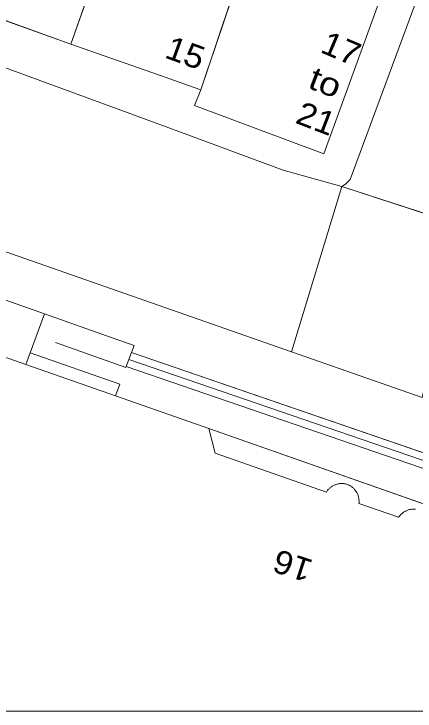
# Model space of a CAD drawing. Extents: x 528790 to 529292, y 179350 to 179856.
# Drawn here: x 529100.89 to 529126.67, y 179356.02 to 179400.83 of the extents above; entities that cross this region are included whole.
import ezdxf

# ---------------------------------------------------------------- set-up
doc = ezdxf.new("R2010")
doc.units = 0
doc.header["$LTSCALE"] = 0.6
for name, color, linetype, lineweight in [('1', 7, 'Continuous', 13), ('2', 7, 'Continuous', 13), ('7', 7, 'Continuous', 13)]:
    doc.layers.add(name, color=color, linetype=linetype, lineweight=lineweight)
doc.layers.add('5', color=7, linetype='Continuous')

msp = doc.modelspace()

# ---------------------------------------------------------------- linework, layer by layer
at = {"layer": '1'}
for points in [[(529153.4, 179460.25), (529147, 179461.55), (529147.5, 179461.3), (529147.9, 179460.65), (529148, 179460.25), (529148.15, 179459.8), (529148.05, 179459.25), (529122.5, 179390.2), (529122.2, 179389.9), (529121.95, 179389.75), (529129.75, 179387.2), (529129.6, 179387.45), (529129.55, 179387.75), (529129.55, 179388), (529129.6, 179388.25), (529151.6, 179448.1)], [(529080, 179405.2), (529096.7, 179398.7), (529108.8, 179394.254), (529111.481, 179393.269), (529118.2, 179390.8), (529121.95, 179389.75), (529122.2, 179389.9), (529122.5, 179390.2), (529148.05, 179459.25)], [(529126.2, 179406.7), (529120.8, 179391.85), (529112.5, 179394.95), (529112.9, 179395.95), (529112.105, 179396.231), (529110.606, 179396.76), (529104.55, 179398.9), (529081.7, 179407.1)], [(529082.78, 179391.7), (529118.73, 179379.12), (529121.95, 179389.75), (529118.2, 179390.8), (529111.481, 179393.269), (529108.8, 179394.254), (529096.7, 179398.7)], [(529127.13, 179376.18), (529118.73, 179379.12), (529082.78, 179391.7)], [(529084.94, 179384.18), (529101.65, 179378.31), (529101.93, 179379.06), (529102.86, 179381.55), (529088.9, 179386.48)], [(529088.21, 179386.8), (529088.54, 179386.66), (529088.9, 179386.48), (529102.86, 179381.55), (529107.2, 179380.02), (529108.61, 179379.52), (529108.44, 179379.07), (529135.26, 179369.85), (529135.32, 179370.03), (529140.32, 179368.27), (529140.62, 179368.17), (529140.91, 179368.05), (529141.19, 179367.93), (529141.47, 179367.79), (529141.79, 179367.61), (529142.06, 179367.45), (529142.32, 179367.28), (529142.67, 179367.02)], [(529113.41, 179374.18), (529107.42, 179376.28), (529101.65, 179378.31), (529084.94, 179384.18)], [(529134.94, 179368.95), (529108.11, 179378.17), (529108.44, 179379.07), (529108.61, 179379.52), (529107.2, 179380.02), (529102.86, 179381.55), (529101.93, 179379.06), (529107.69, 179377.03), (529107.42, 179376.28), (529113.41, 179374.18), (529135.36, 179366.48)], [(529126.7, 179369.01), (529126.65, 179369.01), (529126.6, 179369.01), (529126.55, 179369.01), (529126.5, 179369.01), (529126.45, 179369), (529126.4, 179368.99), (529126.35, 179368.98), (529126.3, 179368.97), (529126.25, 179368.95), (529126.2, 179368.94), (529126.15, 179368.92), (529126.11, 179368.9), (529126.06, 179368.88), (529126.02, 179368.85), (529125.97, 179368.83), (529125.93, 179368.8), (529125.89, 179368.77), (529125.85, 179368.74), (529125.81, 179368.71), (529125.77, 179368.67), (529125.74, 179368.64), (529125.7, 179368.6), (529125.67, 179368.56), (529125.64, 179368.52), (529125.61, 179368.48), (529123.06, 179369.37), (529123.07, 179369.42), (529123.07, 179369.47), (529123.07, 179369.52), (529123.07, 179369.56), (529123.06, 179369.61), (529123.06, 179369.66), (529123.05, 179369.71), (529123.04, 179369.75), (529123.03, 179369.8), (529123.01, 179369.85), (529123, 179369.89), (529122.98, 179369.94), (529122.96, 179369.98), (529122.94, 179370.02), (529122.92, 179370.07), (529122.89, 179370.11), (529122.87, 179370.15), (529122.84, 179370.19), (529122.81, 179370.23), (529122.78, 179370.27), (529122.75, 179370.3), (529122.71, 179370.34), (529122.68, 179370.37), (529122.64, 179370.4), (529122.61, 179370.43), (529122.57, 179370.46), (529122.53, 179370.49), (529122.49, 179370.51), (529122.44, 179370.53), (529122.4, 179370.55), (529122.36, 179370.57), (529122.31, 179370.59), (529122.22, 179370.62), (529122.18, 179370.63), (529122.13, 179370.63), (529122.08, 179370.64), (529122.03, 179370.64), (529121.98, 179370.65), (529121.94, 179370.65), (529121.89, 179370.64), (529121.84, 179370.64), (529121.79, 179370.63), (529121.75, 179370.63), (529121.7, 179370.62), (529121.65, 179370.6), (529121.6, 179370.59), (529121.56, 179370.57), (529121.51, 179370.56), (529121.47, 179370.54), (529121.43, 179370.52), (529121.38, 179370.49), (529121.34, 179370.47), (529121.3, 179370.44), (529121.26, 179370.42), (529121.22, 179370.39), (529121.19, 179370.36), (529121.15, 179370.32), (529121.12, 179370.29), (529121.08, 179370.26), (529121.05, 179370.22), (529121.02, 179370.18), (529121, 179370.14), (529120.97, 179370.1), (529113.83, 179372.61), (529113.41, 179374.18)], [(529113.41, 179374.18), (529113.83, 179372.61), (529120.97, 179370.1), (529121, 179370.14), (529121.02, 179370.18), (529121.05, 179370.22), (529121.08, 179370.26), (529121.12, 179370.29), (529121.15, 179370.32), (529121.19, 179370.36), (529121.22, 179370.39), (529121.26, 179370.42), (529121.3, 179370.44), (529121.34, 179370.47), (529121.38, 179370.49), (529121.43, 179370.52), (529121.47, 179370.54), (529121.51, 179370.56), (529121.56, 179370.57), (529121.6, 179370.59), (529121.65, 179370.6), (529121.7, 179370.62), (529121.75, 179370.63), (529121.79, 179370.63), (529121.84, 179370.64), (529121.89, 179370.64), (529121.94, 179370.65), (529121.98, 179370.65), (529122.03, 179370.64), (529122.08, 179370.64), (529122.13, 179370.63), (529122.18, 179370.63), (529122.22, 179370.62), (529122.31, 179370.59), (529122.36, 179370.57), (529122.4, 179370.55), (529122.44, 179370.53), (529122.49, 179370.51), (529122.53, 179370.49), (529122.57, 179370.46), (529122.61, 179370.43), (529122.64, 179370.4), (529122.68, 179370.37), (529122.71, 179370.34), (529122.75, 179370.3), (529122.78, 179370.27), (529122.81, 179370.23), (529122.84, 179370.19), (529122.87, 179370.15), (529122.89, 179370.11), (529122.92, 179370.07), (529122.94, 179370.02), (529122.96, 179369.98), (529122.98, 179369.94), (529123, 179369.89), (529123.01, 179369.85), (529123.03, 179369.8), (529123.04, 179369.75), (529123.05, 179369.71), (529123.06, 179369.66), (529123.06, 179369.61), (529123.07, 179369.56), (529123.07, 179369.52), (529123.07, 179369.47), (529123.07, 179369.42), (529123.06, 179369.37), (529125.61, 179368.48), (529125.64, 179368.52), (529125.67, 179368.56), (529125.7, 179368.6), (529125.74, 179368.64), (529125.77, 179368.67), (529125.81, 179368.71), (529125.85, 179368.74), (529125.89, 179368.77), (529125.93, 179368.8), (529125.97, 179368.83), (529126.02, 179368.85), (529126.06, 179368.88), (529126.11, 179368.9), (529126.15, 179368.92), (529126.2, 179368.94), (529126.25, 179368.95), (529126.3, 179368.97), (529126.35, 179368.98), (529126.4, 179368.99), (529126.45, 179369), (529126.5, 179369.01), (529126.55, 179369.01), (529126.6, 179369.01), (529126.65, 179369.01), (529126.7, 179369.01)], [(529135.36, 179366.48), (529113.41, 179374.18)], [(529079.274, 179356.024), (529139.303, 179356.024)]]:
    msp.add_lwpolyline(points, dxfattribs=at)
for points in [[(529083.7, 179412.85), (529081.7, 179407.1), (529104.55, 179398.9), (529107.5, 179407.3), (529108, 179408.85), (529104.5, 179410.1), (529103.8, 179408.05), (529100.4, 179409.2), (529092.6, 179411.95), (529093.3, 179413.85), (529085.05, 179416.71)], [(529126.2, 179406.7), (529114.95, 179410.9), (529113.4, 179411.45), (529111.9, 179407.2), (529116.25, 179405.6), (529114.9, 179401.9), (529112.9, 179395.95), (529112.5, 179394.95), (529120.8, 179391.85)], [(529114.9, 179401.9), (529111.75, 179403), (529112.6, 179405.6), (529107.5, 179407.3), (529104.55, 179398.9), (529110.606, 179396.76), (529112.105, 179396.231), (529112.9, 179395.95)], [(529121.95, 179389.75), (529118.73, 179379.12), (529127.13, 179376.18), (529129.75, 179387.2)], [(529107.69, 179377.03), (529101.93, 179379.06), (529101.65, 179378.31), (529107.42, 179376.28)], [(529134.94, 179368.95), (529135.21, 179369.71), (529135.26, 179369.85), (529108.44, 179379.07), (529108.11, 179378.17)]]:
    msp.add_lwpolyline(points, close=True, dxfattribs=at)
at = {"layer": '2'}
for p, q in [((529081.7, 179407.1), (529104.55, 179398.9)), ((529107.5, 179407.3), (529104.55, 179398.9)), ((529114.9, 179401.9), (529112.9, 179395.95)), ((529121.95, 179389.75), (529118.73, 179379.12)), ((529129.75, 179387.2), (529121.95, 179389.75)), ((529101.93, 179379.06), (529102.86, 179381.55)), ((529107.2, 179380.02), (529102.86, 179381.55)), ((529107.2, 179380.02), (529108.61, 179379.52)), ((529108.44, 179379.07), (529108.61, 179379.52)), ((529101.93, 179379.06), (529101.65, 179378.31)), ((529108.11, 179378.17), (529108.44, 179379.07)), ((529108.44, 179379.07), (529135.26, 179369.85)), ((529118.73, 179379.12), (529127.13, 179376.18)), ((529135.1, 179369.4), (529108.28, 179378.62)), ((529107.42, 179376.28), (529101.65, 179378.31)), ((529134.94, 179368.95), (529108.11, 179378.17)), ((529113.41, 179374.18), (529107.42, 179376.28)), ((529135.36, 179366.48), (529113.41, 179374.18))]:
    msp.add_line(p, q, dxfattribs=at)
for points in [[(529147, 179461.55), (529147.5, 179461.3), (529147.9, 179460.65), (529148, 179460.25), (529148.15, 179459.8), (529148.05, 179459.25), (529122.5, 179390.2), (529122.2, 179389.9), (529121.95, 179389.75)], [(529112.9, 179395.95), (529112.5, 179394.95), (529120.8, 179391.85), (529126.2, 179406.7)], [(529121.95, 179389.75), (529118.2, 179390.8), (529111.481, 179393.269), (529108.8, 179394.254), (529096.7, 179398.7), (529080, 179405.2), (529079.5, 179405.65)], [(529104.55, 179398.9), (529110.606, 179396.76), (529112.105, 179396.231), (529112.9, 179395.95)], [(529082.78, 179391.7), (529118.73, 179379.12)], [(529102.86, 179381.55), (529088.9, 179386.48), (529088.54, 179386.66), (529088.21, 179386.8), (529087.88, 179386.93), (529087.55, 179387.04), (529087.2, 179387.14), (529086.86, 179387.23), (529086.51, 179387.3), (529086.16, 179387.36), (529085.81, 179387.4), (529085.46, 179387.43), (529085.1, 179387.45), (529084.75, 179387.45)], [(529101.65, 179378.31), (529084.94, 179384.18), (529083.2, 179384.58), (529082.23, 179384.67), (529081.25, 179384.64), (529080.48, 179384.52), (529079.72, 179384.31), (529078.99, 179384.02), (529078.28, 179383.68), (529077.5, 179383.19), (529076.78, 179382.58), (529076.14, 179381.9), (529075.57, 179381.16), (529075.14, 179380.47), (529074.79, 179379.72)], [(529103.57, 179379.71), (529108.09, 179378.11), (529108.11, 179378.17)], [(529107.42, 179376.28), (529107.69, 179377.03), (529101.93, 179379.06)], [(529122.75, 179370.3), (529122.71, 179370.34), (529122.68, 179370.37), (529122.64, 179370.4), (529122.61, 179370.43), (529122.57, 179370.46), (529122.53, 179370.49), (529122.49, 179370.51), (529122.44, 179370.53), (529122.4, 179370.55), (529122.36, 179370.57), (529122.31, 179370.59), (529122.22, 179370.62), (529122.18, 179370.63), (529122.13, 179370.63), (529122.08, 179370.64), (529122.03, 179370.64), (529121.98, 179370.65), (529121.94, 179370.65), (529121.89, 179370.64), (529121.84, 179370.64), (529121.79, 179370.63), (529121.75, 179370.63), (529121.7, 179370.62), (529121.65, 179370.6), (529121.6, 179370.59), (529121.56, 179370.57), (529121.51, 179370.56), (529121.47, 179370.54), (529121.43, 179370.52), (529121.38, 179370.49), (529121.34, 179370.47), (529121.3, 179370.44), (529121.26, 179370.42), (529121.22, 179370.39), (529121.19, 179370.36), (529121.15, 179370.32), (529121.12, 179370.29), (529121.08, 179370.26), (529121.05, 179370.22), (529121.02, 179370.18), (529121, 179370.14), (529120.97, 179370.1), (529113.83, 179372.61), (529113.41, 179374.18)], [(529126.7, 179369.01), (529126.65, 179369.01), (529126.6, 179369.01), (529126.55, 179369.01), (529126.5, 179369.01), (529126.45, 179369), (529126.4, 179368.99), (529126.35, 179368.98), (529126.3, 179368.97), (529126.25, 179368.95), (529126.2, 179368.94), (529126.15, 179368.92), (529126.11, 179368.9), (529126.06, 179368.88), (529126.02, 179368.85), (529125.97, 179368.83), (529125.93, 179368.8), (529125.89, 179368.77), (529125.85, 179368.74), (529125.81, 179368.71), (529125.77, 179368.67), (529125.74, 179368.64), (529125.7, 179368.6), (529125.67, 179368.56), (529125.64, 179368.52), (529125.61, 179368.48), (529123.06, 179369.37), (529123.07, 179369.42), (529123.07, 179369.47), (529123.07, 179369.52), (529123.07, 179369.56), (529123.06, 179369.61), (529123.06, 179369.66), (529123.05, 179369.71), (529123.04, 179369.75), (529123.03, 179369.8), (529123.01, 179369.85), (529123, 179369.89), (529122.98, 179369.94), (529122.96, 179369.98), (529122.94, 179370.02), (529122.92, 179370.07), (529122.89, 179370.11), (529122.87, 179370.15), (529122.84, 179370.19), (529122.81, 179370.23), (529122.78, 179370.27), (529122.75, 179370.3)]]:
    msp.add_lwpolyline(points, dxfattribs=at)
at = {"layer": '7'}
msp.add_lwpolyline([(528790.22, 179356.024), (529290.22, 179356.024), (529290.22, 179856.024), (528790.22, 179856.024)], close=True, dxfattribs=at)

# ---------------------------------------------------------------- texts
at = {"layer": '5'}
for s, rotation, width, p in [('17', 337, 1.1, (529120.5, 179398.4)), ('15', 340, 1.1, (529110.5, 179398.05)), ('to', 339, 1.2, (529119.7, 179396.1)), ('21', 339, 1.1, (529118.9, 179393.85)), ('16', 162, 1.1, (529120.2, 179365.69))]:
    msp.add_text(s, height=1.5, rotation=rotation, dxfattribs=dict(at, width=width)).set_placement(p)

doc.saveas('drawing.dxf')
